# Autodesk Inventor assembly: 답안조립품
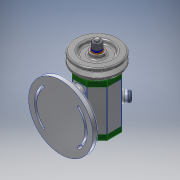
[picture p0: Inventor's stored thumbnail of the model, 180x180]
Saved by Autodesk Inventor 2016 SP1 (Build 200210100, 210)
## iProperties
Created: 2017-06
Part Number: 답안조립품
Material: 일반
Document SubType Name: Assembly
Designer: basic
Author: basic
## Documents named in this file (14)
- C:\Users\basic\Desktop\470608V1007\답안조립품.iam
- C:\Users\basic\Desktop\470608V1007\본체.ipt
- C:\Users\basic\Desktop\470608V1007\축.ipt
- C:\Users\basic\Desktop\470608V1007\베어링 15 x 32 x 9.ipt
- C:\Users\basic\Desktop\470608V1007\키 3 x 3 x 12.ipt
- C:\Users\basic\Desktop\470608V1007\앞커버.ipt
- C:\Users\basic\Desktop\470608V1007\볼트 M4 x 12.ipt
- C:\Users\basic\Desktop\470608V1007\뒤커버.ipt
- C:\Users\basic\Desktop\470608V1007\오일 실 15 25 7.ipt
- C:\Users\basic\Desktop\470608V1007\V벨트풀리.ipt
- C:\Users\basic\Desktop\470608V1007\와셔 8x17.ipt
- C:\Users\basic\Desktop\470608V1007\스프링와셔 8.ipt
- C:\Users\basic\Desktop\470608V1007\너트 M 8.ipt
- C:\Users\basic\Desktop\470608V1007\고무캡.ipt
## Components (2 placed, 2 different names)
1. V벨트풀리:1
2. 고무캡:1
